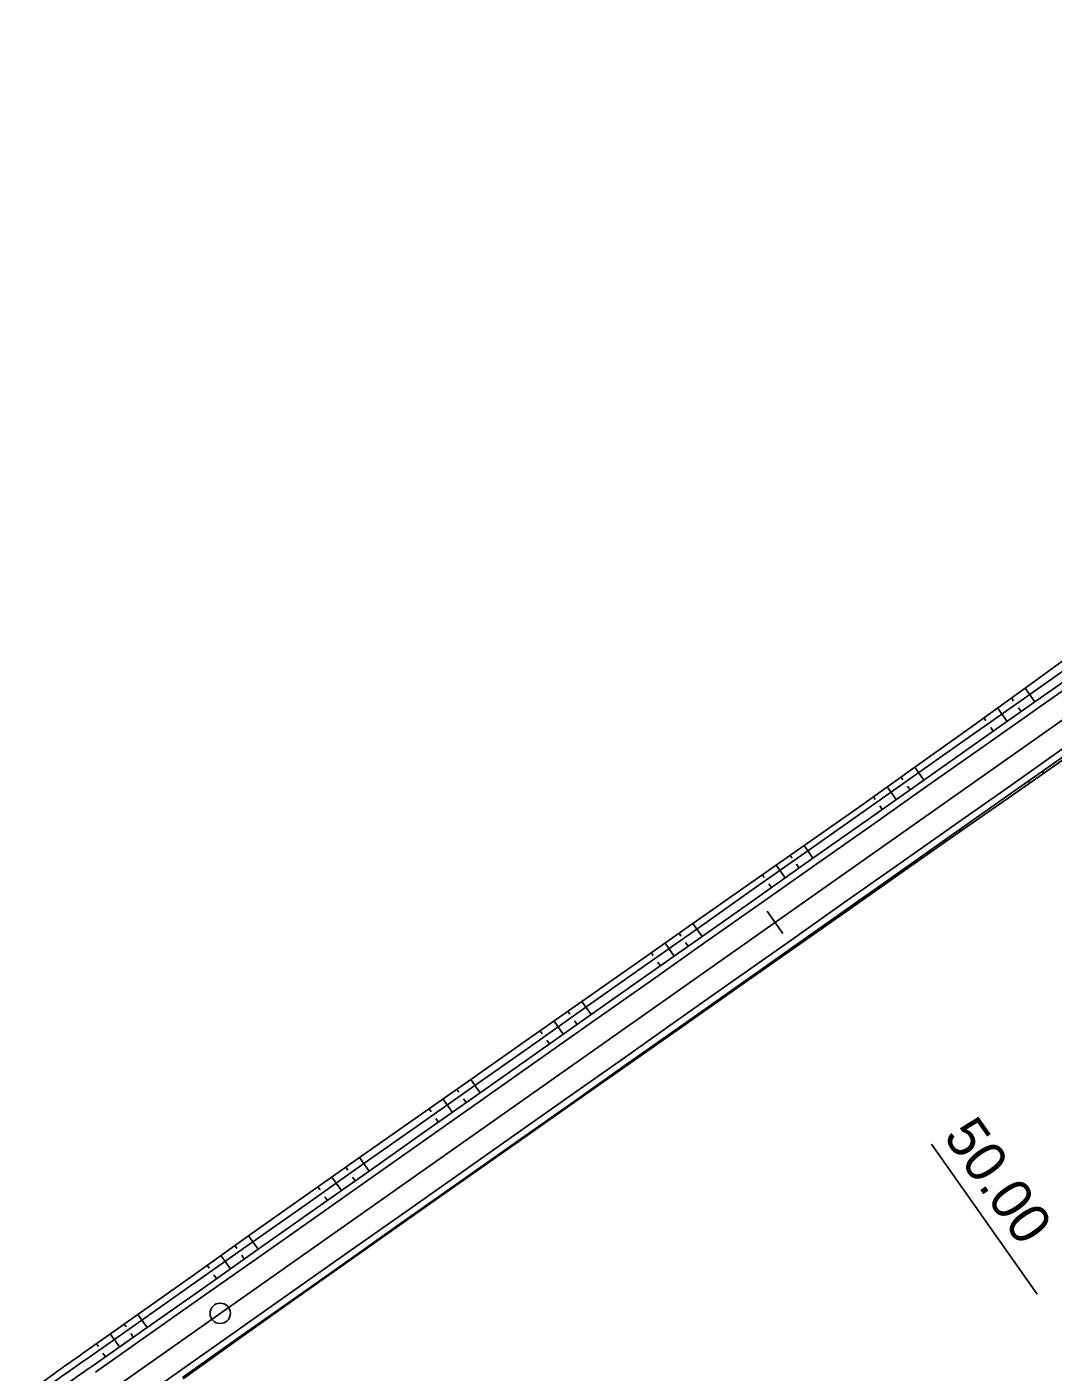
# Model space of a CAD drawing. Extents: x -481656 to -478728, y -1113199 to -1110710.
# Drawn here: x -480468.2 to -480392.6, y -1112820.8 to -1112721.8 of the extents above; entities that cross this region are included whole.
import ezdxf

# ---------------------------------------------------------------- set-up
doc = ezdxf.new("R2010")
doc.units = 0
for name, color, linetype in [('C14_HATCH_SLOPE_L', 7, 'Continuous'), ('C14_HATCH_SLOPE_R', 7, 'Continuous'), ('C14_HECTOMETRY', 7, 'Continuous'), ('C14_HRANA_TELESO', 7, 'Continuous'), ('C14_KORUNA', 7, 'Continuous'), ('C14_OSA', 7, 'Continuous'), ('C14_PRIKOP', 7, 'Continuous'), ('C14_STANICENI', 7, 'Continuous'), ('C14_VOZOVKA', 7, 'Continuous'), ('C14_ZPEVKRAJ', 7, 'Continuous')]:
    doc.layers.add(name, color=color, linetype=linetype)

msp = doc.modelspace()

# ---------------------------------------------------------------- linework, layer by layer
at = {"layer": 'C14_HATCH_SLOPE_L'}
for p, q in [((-480393.945, -1112771.478), (-480394.662, -1112770.461)), ((-480395.989, -1112772.918), (-480396.69, -1112771.922)), ((-480395.514, -1112771.422), (-480395.676, -1112771.192)), ((-480394.967, -1112772.198), (-480395.159, -1112771.926)), ((-480397.55, -1112772.873), (-480397.705, -1112772.653)), ((-480397.011, -1112773.638), (-480397.203, -1112773.366)), ((-480402.12, -1112777.238), (-480402.788, -1112776.289)), ((-480404.163, -1112778.678), (-480404.821, -1112777.744)), ((-480403.665, -1112777.215), (-480403.805, -1112777.017)), ((-480403.141, -1112777.958), (-480403.333, -1112777.686)), ((-480405.704, -1112778.662), (-480405.838, -1112778.471)), ((-480405.185, -1112779.398), (-480405.377, -1112779.126)), ((-480411.836, -1112782.98), (-480411.973, -1112782.786)), ((-480410.294, -1112782.998), (-480410.949, -1112782.068)), ((-480412.337, -1112784.438), (-480412.996, -1112783.503)), ((-480411.316, -1112783.718), (-480411.508, -1112783.446)), ((-480413.882, -1112784.417), (-480414.02, -1112784.22)), ((-480413.359, -1112785.158), (-480413.551, -1112784.886)), ((-480418.468, -1112788.759), (-480419.137, -1112787.809)), ((-480420.017, -1112788.73), (-480420.16, -1112788.527)), ((-480420.512, -1112790.199), (-480421.184, -1112789.245)), ((-480419.49, -1112789.479), (-480419.682, -1112789.206)), ((-480422.062, -1112790.168), (-480422.207, -1112789.963)), ((-480421.533, -1112790.919), (-480421.725, -1112790.646)), ((-480426.642, -1112794.519), (-480427.323, -1112793.553)), ((-480428.197, -1112794.482), (-480428.346, -1112794.271)), ((-480430.242, -1112795.92), (-480430.393, -1112795.707)), ((-480428.686, -1112795.959), (-480429.37, -1112794.989)), ((-480427.664, -1112795.239), (-480427.856, -1112794.966)), ((-480429.708, -1112796.679), (-480429.9, -1112796.406)), ((-480434.817, -1112800.279), (-480435.51, -1112799.296)), ((-480436.86, -1112801.719), (-480437.556, -1112800.731)), ((-480436.378, -1112800.234), (-480436.533, -1112800.013)), ((-480435.838, -1112800.999), (-480436.03, -1112800.727)), ((-480438.423, -1112801.672), (-480438.58, -1112801.449)), ((-480437.882, -1112802.439), (-480438.074, -1112802.167)), ((-480442.991, -1112806.04), (-480443.697, -1112805.037)), ((-480445.034, -1112807.48), (-480445.739, -1112806.479)), ((-480444.558, -1112805.986), (-480444.718, -1112805.758)), ((-480444.013, -1112806.76), (-480444.205, -1112806.488)), ((-480446.6, -1112807.428), (-480446.76, -1112807.2)), ((-480446.056, -1112808.2), (-480446.248, -1112807.928)), ((-480452.728, -1112811.752), (-480452.884, -1112811.53)), ((-480451.165, -1112811.8), (-480451.866, -1112810.806)), ((-480453.209, -1112813.24), (-480453.903, -1112812.255)), ((-480452.187, -1112812.52), (-480452.379, -1112812.248)), ((-480454.768, -1112813.198), (-480454.921, -1112812.98)), ((-480454.23, -1112813.96), (-480454.422, -1112813.688)), ((-480459.339, -1112817.56), (-480460.019, -1112816.595)), ((-480460.892, -1112817.527), (-480461.039, -1112817.318)), ((-480461.383, -1112819), (-480462.059, -1112818.041)), ((-480460.361, -1112818.28), (-480460.553, -1112818.008)), ((-480462.934, -1112818.97), (-480463.078, -1112818.764)), ((-480462.405, -1112819.72), (-480462.597, -1112819.448))]:
    msp.add_line(p, q, dxfattribs=at)
at = {"layer": 'C14_HATCH_SLOPE_R'}
for p, q in [((-480393.397, -1112776.596), (-480393.291, -1112776.746)), ((-480394.419, -1112777.316), (-480394.368, -1112777.388)), ((-480394.316, -1112777.461), (-480394.316, -1112777.461)), ((-480399.527, -1112780.916), (-480399.442, -1112781.037)), ((-480400.549, -1112781.636), (-480400.508, -1112781.694)), ((-480400.467, -1112781.753), (-480400.467, -1112781.753)), ((-480401.571, -1112782.356), (-480401.492, -1112782.469)), ((-480402.593, -1112783.076), (-480402.555, -1112783.13)), ((-480402.517, -1112783.185), (-480402.517, -1112783.185)), ((-480407.702, -1112786.677), (-480407.634, -1112786.773)), ((-480408.723, -1112787.397), (-480408.69, -1112787.444)), ((-480408.657, -1112787.491), (-480408.657, -1112787.491)), ((-480410.767, -1112788.837), (-480410.735, -1112788.882)), ((-480409.745, -1112788.117), (-480409.68, -1112788.209)), ((-480410.703, -1112788.927), (-480410.703, -1112788.927)), ((-480415.876, -1112792.437), (-480415.819, -1112792.517)), ((-480416.898, -1112793.157), (-480416.87, -1112793.196)), ((-480416.842, -1112793.235), (-480416.842, -1112793.235)), ((-480418.941, -1112794.597), (-480418.915, -1112794.634)), ((-480418.889, -1112794.672), (-480418.889, -1112794.672)), ((-480417.919, -1112793.877), (-480417.866, -1112793.954)), ((-480424.05, -1112798.197), (-480424.005, -1112798.262)), ((-480426.094, -1112799.637), (-480426.051, -1112799.698)), ((-480425.072, -1112798.917), (-480425.05, -1112798.948)), ((-480425.028, -1112798.98), (-480425.028, -1112798.98)), ((-480427.116, -1112800.357), (-480427.095, -1112800.386)), ((-480427.074, -1112800.416), (-480427.074, -1112800.416)), ((-480433.246, -1112804.678), (-480433.229, -1112804.702)), ((-480432.224, -1112803.958), (-480432.189, -1112804.008)), ((-480434.268, -1112805.398), (-480434.236, -1112805.444)), ((-480433.212, -1112804.726), (-480433.212, -1112804.726)), ((-480435.29, -1112806.118), (-480435.274, -1112806.14)), ((-480435.259, -1112806.162), (-480435.259, -1112806.162)), ((-480441.42, -1112810.438), (-480441.404, -1112810.46)), ((-480441.389, -1112810.483), (-480441.389, -1112810.483)), ((-480440.399, -1112809.718), (-480440.367, -1112809.763)), ((-480442.442, -1112811.158), (-480442.41, -1112811.204)), ((-480443.464, -1112811.878), (-480443.448, -1112811.901)), ((-480443.431, -1112811.924), (-480443.431, -1112811.924)), ((-480448.573, -1112815.478), (-480448.538, -1112815.528)), ((-480449.595, -1112816.198), (-480449.576, -1112816.226)), ((-480449.556, -1112816.253), (-480449.556, -1112816.253)), ((-480450.616, -1112816.918), (-480450.574, -1112816.979)), ((-480451.638, -1112817.639), (-480451.614, -1112817.672)), ((-480451.591, -1112817.705), (-480451.591, -1112817.705))]:
    msp.add_line(p, q, dxfattribs=at)
at = {"layer": 'C14_HECTOMETRY'}
msp.add_circle((-480453.956, -1112816.519), 0.75, dxfattribs=at)
at = {"layer": 'C14_HRANA_TELESO'}
for p, q in [((-480394.662, -1112770.461), (-480390.609, -1112767.532)), ((-480398.719, -1112773.384), (-480394.662, -1112770.461)), ((-480402.788, -1112776.289), (-480398.719, -1112773.384)), ((-480395.342, -1112778.176), (-480391.241, -1112775.315)), ((-480406.855, -1112779.199), (-480402.788, -1112776.289)), ((-480399.442, -1112781.037), (-480395.342, -1112778.176)), ((-480410.949, -1112782.068), (-480406.855, -1112779.199)), ((-480403.541, -1112783.9), (-480399.442, -1112781.037)), ((-480415.044, -1112784.938), (-480410.949, -1112782.068)), ((-480407.634, -1112786.773), (-480403.541, -1112783.9)), ((-480419.137, -1112787.809), (-480415.044, -1112784.938)), ((-480411.727, -1112789.645), (-480407.634, -1112786.773)), ((-480423.23, -1112790.681), (-480419.137, -1112787.809)), ((-480415.819, -1112792.517), (-480411.727, -1112789.645)), ((-480427.323, -1112793.553), (-480423.23, -1112790.681)), ((-480419.912, -1112795.39), (-480415.819, -1112792.517)), ((-480431.416, -1112796.425), (-480427.323, -1112793.553)), ((-480424.005, -1112798.262), (-480419.912, -1112795.39)), ((-480435.51, -1112799.296), (-480431.416, -1112796.425)), ((-480428.097, -1112801.134), (-480424.005, -1112798.262)), ((-480439.603, -1112802.167), (-480435.51, -1112799.296)), ((-480432.189, -1112804.008), (-480428.097, -1112801.134)), ((-480443.697, -1112805.037), (-480439.603, -1112802.167)), ((-480436.282, -1112806.88), (-480432.189, -1112804.008)), ((-480447.781, -1112807.921), (-480443.697, -1112805.037)), ((-480440.367, -1112809.763), (-480436.282, -1112806.88)), ((-480451.866, -1112810.806), (-480447.781, -1112807.921)), ((-480444.453, -1112812.645), (-480440.367, -1112809.763)), ((-480455.94, -1112813.704), (-480451.866, -1112810.806)), ((-480448.538, -1112815.528), (-480444.453, -1112812.645)), ((-480460.019, -1112816.595), (-480455.94, -1112813.704)), ((-480452.609, -1112818.431), (-480448.538, -1112815.528)), ((-480464.098, -1112819.487), (-480460.019, -1112816.595)), ((-480456.678, -1112821.337), (-480452.609, -1112818.431))]:
    msp.add_line(p, q, dxfattribs=at)
msp.add_arc((-480406.481, -1112903.285), 101.694, 124.51148, 127.36704, dxfattribs=at)
at = {"layer": 'C14_KORUNA'}
for p, q in [((-480393.945, -1112771.478), (-480389.858, -1112768.597)), ((-480398.032, -1112774.358), (-480393.945, -1112771.478)), ((-480402.12, -1112777.238), (-480398.032, -1112774.358)), ((-480395.44, -1112778.036), (-480391.353, -1112775.156)), ((-480406.207, -1112780.118), (-480402.12, -1112777.238)), ((-480399.527, -1112780.916), (-480395.44, -1112778.036)), ((-480410.294, -1112782.998), (-480406.207, -1112780.118)), ((-480403.615, -1112783.796), (-480399.527, -1112780.916)), ((-480414.381, -1112785.878), (-480410.294, -1112782.998)), ((-480407.702, -1112786.677), (-480403.615, -1112783.796)), ((-480418.468, -1112788.759), (-480414.381, -1112785.878)), ((-480411.789, -1112789.557), (-480407.702, -1112786.677)), ((-480422.555, -1112791.639), (-480418.468, -1112788.759)), ((-480415.876, -1112792.437), (-480411.789, -1112789.557)), ((-480426.642, -1112794.519), (-480422.555, -1112791.639)), ((-480419.963, -1112795.317), (-480415.876, -1112792.437)), ((-480430.729, -1112797.399), (-480426.642, -1112794.519)), ((-480424.05, -1112798.197), (-480419.963, -1112795.317)), ((-480434.817, -1112800.279), (-480430.729, -1112797.399)), ((-480428.137, -1112801.078), (-480424.05, -1112798.197)), ((-480438.904, -1112803.159), (-480434.817, -1112800.279)), ((-480432.224, -1112803.958), (-480428.137, -1112801.078)), ((-480442.991, -1112806.04), (-480438.904, -1112803.159)), ((-480436.312, -1112806.838), (-480432.224, -1112803.958)), ((-480447.078, -1112808.92), (-480442.991, -1112806.04)), ((-480440.399, -1112809.718), (-480436.312, -1112806.838)), ((-480451.165, -1112811.8), (-480447.078, -1112808.92)), ((-480444.486, -1112812.598), (-480440.399, -1112809.718)), ((-480455.252, -1112814.68), (-480451.165, -1112811.8)), ((-480448.573, -1112815.478), (-480444.486, -1112812.598)), ((-480459.339, -1112817.56), (-480455.252, -1112814.68)), ((-480452.66, -1112818.359), (-480448.573, -1112815.478)), ((-480463.426, -1112820.441), (-480459.339, -1112817.56)), ((-480456.747, -1112821.239), (-480452.66, -1112818.359))]:
    msp.add_line(p, q, dxfattribs=at)
msp.add_arc((-480406.585, -1112904.079), 101.125, 124.20019, 127.05879, dxfattribs=at)
at = {"layer": 'C14_OSA'}
msp.add_line((-480462.955, -1112822.861), (-480319.487, -1112721.759), dxfattribs=at)
at = {"layer": 'C14_PRIKOP'}
for p, q in [((-480394.329, -1112770.933), (-480390.242, -1112768.053)), ((-480398.416, -1112773.813), (-480394.329, -1112770.933)), ((-480402.504, -1112776.693), (-480398.416, -1112773.813)), ((-480406.591, -1112779.573), (-480402.504, -1112776.693)), ((-480410.678, -1112782.453), (-480406.591, -1112779.573)), ((-480414.765, -1112785.334), (-480410.678, -1112782.453)), ((-480418.852, -1112788.214), (-480414.765, -1112785.334)), ((-480422.939, -1112791.094), (-480418.852, -1112788.214)), ((-480427.026, -1112793.974), (-480422.939, -1112791.094)), ((-480431.113, -1112796.854), (-480427.026, -1112793.974)), ((-480435.201, -1112799.734), (-480431.113, -1112796.854)), ((-480439.288, -1112802.615), (-480435.201, -1112799.734)), ((-480443.375, -1112805.495), (-480439.288, -1112802.615)), ((-480447.462, -1112808.375), (-480443.375, -1112805.495)), ((-480451.549, -1112811.255), (-480447.462, -1112808.375)), ((-480455.636, -1112814.135), (-480451.549, -1112811.255)), ((-480459.723, -1112817.016), (-480455.636, -1112814.135)), ((-480463.81, -1112819.896), (-480459.723, -1112817.016))]:
    msp.add_line(p, q, dxfattribs=at)
msp.add_arc((-480406.78, -1112903.808), 101.458, 124.20143, 127.05815, dxfattribs=at)
at = {"layer": 'C14_STANICENI'}
for p, q in [((-480412.509, -1112788.535), (-480413.661, -1112786.9)), ((-480401.564, -1112804.066), (-480393.788, -1112815.101))]:
    msp.add_line(p, q, dxfattribs=at)
at = {"layer": 'C14_VOZOVKA'}
for p, q in [((-480393.657, -1112771.886), (-480389.57, -1112769.006)), ((-480397.744, -1112774.766), (-480393.657, -1112771.886)), ((-480401.832, -1112777.647), (-480397.744, -1112774.766)), ((-480395.728, -1112777.627), (-480391.641, -1112774.747)), ((-480405.919, -1112780.527), (-480401.832, -1112777.647)), ((-480399.815, -1112780.508), (-480395.728, -1112777.627)), ((-480410.006, -1112783.407), (-480405.919, -1112780.527)), ((-480403.903, -1112783.388), (-480399.815, -1112780.508)), ((-480414.093, -1112786.287), (-480410.006, -1112783.407)), ((-480407.99, -1112786.268), (-480403.903, -1112783.388)), ((-480418.18, -1112789.167), (-480414.093, -1112786.287)), ((-480412.077, -1112789.148), (-480407.99, -1112786.268)), ((-480422.267, -1112792.047), (-480418.18, -1112789.167)), ((-480416.164, -1112792.028), (-480412.077, -1112789.148)), ((-480426.354, -1112794.928), (-480422.267, -1112792.047)), ((-480420.251, -1112794.908), (-480416.164, -1112792.028)), ((-480430.441, -1112797.808), (-480426.354, -1112794.928)), ((-480424.338, -1112797.789), (-480420.251, -1112794.908)), ((-480434.529, -1112800.688), (-480430.441, -1112797.808)), ((-480428.425, -1112800.669), (-480424.338, -1112797.789)), ((-480438.616, -1112803.568), (-480434.529, -1112800.688)), ((-480432.512, -1112803.549), (-480428.425, -1112800.669)), ((-480442.703, -1112806.448), (-480438.616, -1112803.568)), ((-480436.6, -1112806.429), (-480432.512, -1112803.549)), ((-480446.79, -1112809.329), (-480442.703, -1112806.448)), ((-480440.687, -1112809.309), (-480436.6, -1112806.429)), ((-480450.877, -1112812.209), (-480446.79, -1112809.329)), ((-480444.774, -1112812.189), (-480440.687, -1112809.309)), ((-480454.964, -1112815.089), (-480450.877, -1112812.209)), ((-480448.861, -1112815.07), (-480444.774, -1112812.189)), ((-480459.051, -1112817.969), (-480454.964, -1112815.089)), ((-480452.948, -1112817.95), (-480448.861, -1112815.07)), ((-480463.138, -1112820.849), (-480459.051, -1112817.969)), ((-480457.035, -1112820.83), (-480452.948, -1112817.95)), ((-480461.122, -1112823.71), (-480457.035, -1112820.83))]:
    msp.add_line(p, q, dxfattribs=at)
at = {"layer": 'C14_ZPEVKRAJ'}
for p, q in [((-480393.657, -1112771.886), (-480389.57, -1112769.006)), ((-480397.744, -1112774.766), (-480393.657, -1112771.886)), ((-480401.832, -1112777.647), (-480397.744, -1112774.766)), ((-480395.728, -1112777.627), (-480391.641, -1112774.747)), ((-480405.919, -1112780.527), (-480401.832, -1112777.647)), ((-480399.815, -1112780.508), (-480395.728, -1112777.627)), ((-480410.006, -1112783.407), (-480405.919, -1112780.527)), ((-480403.903, -1112783.388), (-480399.815, -1112780.508)), ((-480414.093, -1112786.287), (-480410.006, -1112783.407)), ((-480407.99, -1112786.268), (-480403.903, -1112783.388)), ((-480418.18, -1112789.167), (-480414.093, -1112786.287)), ((-480412.077, -1112789.148), (-480407.99, -1112786.268)), ((-480422.267, -1112792.047), (-480418.18, -1112789.167)), ((-480416.164, -1112792.028), (-480412.077, -1112789.148)), ((-480426.354, -1112794.928), (-480422.267, -1112792.047)), ((-480420.251, -1112794.908), (-480416.164, -1112792.028)), ((-480430.441, -1112797.808), (-480426.354, -1112794.928)), ((-480424.338, -1112797.789), (-480420.251, -1112794.908)), ((-480434.529, -1112800.688), (-480430.441, -1112797.808)), ((-480428.425, -1112800.669), (-480424.338, -1112797.789)), ((-480438.616, -1112803.568), (-480434.529, -1112800.688)), ((-480432.512, -1112803.549), (-480428.425, -1112800.669)), ((-480442.703, -1112806.448), (-480438.616, -1112803.568)), ((-480436.6, -1112806.429), (-480432.512, -1112803.549)), ((-480446.79, -1112809.329), (-480442.703, -1112806.448)), ((-480440.687, -1112809.309), (-480436.6, -1112806.429)), ((-480450.877, -1112812.209), (-480446.79, -1112809.329)), ((-480444.774, -1112812.189), (-480440.687, -1112809.309)), ((-480454.964, -1112815.089), (-480450.877, -1112812.209)), ((-480448.861, -1112815.07), (-480444.774, -1112812.189)), ((-480459.051, -1112817.969), (-480454.964, -1112815.089)), ((-480452.948, -1112817.95), (-480448.861, -1112815.07)), ((-480463.138, -1112820.849), (-480459.051, -1112817.969)), ((-480457.035, -1112820.83), (-480452.948, -1112817.95)), ((-480461.122, -1112823.71), (-480457.035, -1112820.83))]:
    msp.add_line(p, q, dxfattribs=at)

# ---------------------------------------------------------------- texts
at = {"layer": 'C14_STANICENI'}
msp.add_text('50.00', height=2.999, rotation=305.17217, dxfattribs=at).set_placement((-480400.747, -1112803.489))

doc.saveas('drawing.dxf')
